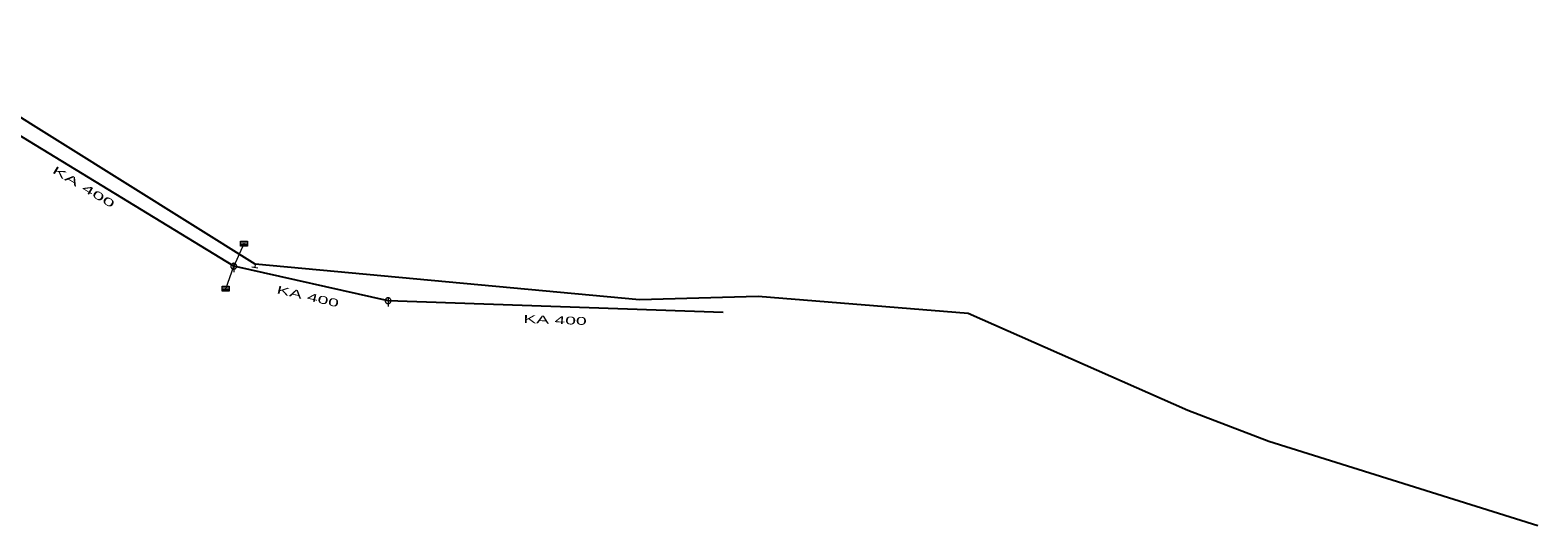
# Model space of a CAD drawing. Extents: x -687515 to -686506, y -974029 to -973461.
# Drawn here: x -686635.2 to -686506.3, y -973717.7 to -973675.3 of the extents above; entities that cross this region are included whole.
import ezdxf
from ezdxf.enums import TextEntityAlignment as Align

# ---------------------------------------------------------------- set-up
doc = ezdxf.new("R2010")
doc.units = 0
doc.header["$LTSCALE"] = 0.27
for name, color, linetype, lineweight in [('1', 7, 'Continuous', 13), ('11', 7, 'Continuous', 13), ('14', 7, 'Continuous', 25), ('17', 7, 'Continuous', 25), ('22', 7, 'Continuous', 13), ('34', 7, 'Continuous', 13)]:
    doc.layers.add(name, color=color, linetype=linetype, lineweight=lineweight)

msp = doc.modelspace()

# ---------------------------------------------------------------- linework, layer by layer
at = {"layer": '11'}
for p in [(-686616.94, -973693.61), (-686618.48, -973697.46)]:
    msp.add_line(p, (-686617.8, -973695.54), dxfattribs=at)
at = {"layer": '14'}
for p, q in [((-686617.8, -973695.539), (-686642.71, -973680.34)), ((-686604.609, -973698.489), (-686617.8, -973695.539)), ((-686575.969, -973699.48), (-686604.609, -973698.489))]:
    msp.add_line(p, q, dxfattribs=at)
at = {"layer": '14', "lineweight": 13}
msp.add_line((-686615.962, -973695.359), (-686616, -973695.659), dxfattribs=at)
at = {"layer": '17'}
msp.add_lwpolyline([(-686506.346, -973717.746), (-686529.344, -973710.524), (-686536.247, -973707.872), (-686555.026, -973699.577), (-686572.978, -973698.129), (-686583.112, -973698.418), (-686615.962, -973695.359), (-686637.993, -973681.581), (-686653.818, -973675.34), (-686693.532, -973676.405), (-686696.345, -973676.48)], dxfattribs=at)
at = {"layer": '22'}
for p, q in [((-686617.235, -973693.539), (-686616.637, -973693.539)), ((-686617.235, -973693.684), (-686616.637, -973693.684)), ((-686617.799, -973695.287), (-686617.8, -973696.031)), ((-686618.775, -973697.389), (-686618.177, -973697.389)), ((-686618.775, -973697.534), (-686618.177, -973697.534)), ((-686604.608, -973698.237), (-686604.609, -973698.98))]:
    msp.add_line(p, q, dxfattribs=at)
for points in [[(-686617.235, -973693.393), (-686616.637, -973693.393), (-686616.637, -973693.83), (-686617.235, -973693.83)], [(-686617.548, -973695.539), (-686617.549, -973695.513), (-686617.553, -973695.487), (-686617.559, -973695.461), (-686617.569, -973695.437), (-686617.581, -973695.413), (-686617.595, -973695.391), (-686617.612, -973695.37), (-686617.63, -973695.352), (-686617.651, -973695.335), (-686617.673, -973695.321), (-686617.697, -973695.309), (-686617.721, -973695.299), (-686617.747, -973695.293), (-686617.773, -973695.289), (-686617.799, -973695.287), (-686617.825, -973695.288), (-686617.851, -973695.292), (-686617.877, -973695.298), (-686617.902, -973695.308), (-686617.925, -973695.32), (-686617.947, -973695.334), (-686617.968, -973695.351), (-686617.986, -973695.369), (-686618.003, -973695.39), (-686618.017, -973695.412), (-686618.029, -973695.436), (-686618.039, -973695.46), (-686618.046, -973695.486), (-686618.05, -973695.512), (-686618.052, -973695.538), (-686618.051, -973695.564), (-686618.047, -973695.59), (-686618.04, -973695.616), (-686618.03, -973695.641), (-686618.018, -973695.664), (-686618.004, -973695.686), (-686617.987, -973695.707), (-686617.969, -973695.725), (-686617.948, -973695.742), (-686617.926, -973695.756), (-686617.903, -973695.768), (-686617.878, -973695.778), (-686617.852, -973695.785), (-686617.826, -973695.789), (-686617.8, -973695.791), (-686617.774, -973695.79), (-686617.748, -973695.786), (-686617.722, -973695.779), (-686617.698, -973695.769), (-686617.674, -973695.757), (-686617.652, -973695.743), (-686617.631, -973695.726), (-686617.613, -973695.708), (-686617.596, -973695.687), (-686617.582, -973695.665), (-686617.57, -973695.642), (-686617.56, -973695.617), (-686617.554, -973695.591), (-686617.55, -973695.565)], [(-686618.775, -973697.243), (-686618.177, -973697.243), (-686618.177, -973697.679), (-686618.775, -973697.679)], [(-686604.357, -973698.489), (-686604.358, -973698.463), (-686604.362, -973698.437), (-686604.368, -973698.411), (-686604.378, -973698.387), (-686604.39, -973698.363), (-686604.404, -973698.341), (-686604.421, -973698.32), (-686604.439, -973698.302), (-686604.46, -973698.285), (-686604.482, -973698.271), (-686604.506, -973698.259), (-686604.53, -973698.249), (-686604.556, -973698.243), (-686604.582, -973698.239), (-686604.608, -973698.237), (-686604.634, -973698.238), (-686604.66, -973698.242), (-686604.686, -973698.248), (-686604.711, -973698.258), (-686604.734, -973698.27), (-686604.756, -973698.284), (-686604.777, -973698.301), (-686604.795, -973698.319), (-686604.812, -973698.34), (-686604.826, -973698.362), (-686604.838, -973698.386), (-686604.848, -973698.41), (-686604.855, -973698.436), (-686604.859, -973698.462), (-686604.861, -973698.488), (-686604.86, -973698.514), (-686604.856, -973698.54), (-686604.849, -973698.566), (-686604.839, -973698.591), (-686604.827, -973698.614), (-686604.813, -973698.636), (-686604.796, -973698.657), (-686604.778, -973698.675), (-686604.757, -973698.692), (-686604.735, -973698.706), (-686604.712, -973698.718), (-686604.687, -973698.728), (-686604.661, -973698.735), (-686604.635, -973698.739), (-686604.609, -973698.74), (-686604.583, -973698.74), (-686604.557, -973698.736), (-686604.531, -973698.729), (-686604.507, -973698.719), (-686604.483, -973698.707), (-686604.461, -973698.693), (-686604.44, -973698.676), (-686604.422, -973698.658), (-686604.405, -973698.637), (-686604.391, -973698.615), (-686604.379, -973698.592), (-686604.369, -973698.567), (-686604.363, -973698.541), (-686604.359, -973698.515)]]:
    msp.add_lwpolyline(points, close=True, dxfattribs=at)
at = {"layer": '34'}
msp.add_line((-686615.753, -973695.69), (-686616.246, -973695.627), dxfattribs=at)

# ---------------------------------------------------------------- texts
at = {"layer": '1'}
for rotation, width, p in [(329, 2.05, (-686630.798, -973689.039)), (347, 1.85, (-686611.537, -973698.447)), (358, 1.85, (-686590.351, -973700.469))]:
    msp.add_text('KA 400', height=0.6667, rotation=rotation, dxfattribs=dict(at, width=width)).set_placement(p, align=Align.CENTER)

doc.saveas('drawing.dxf')
